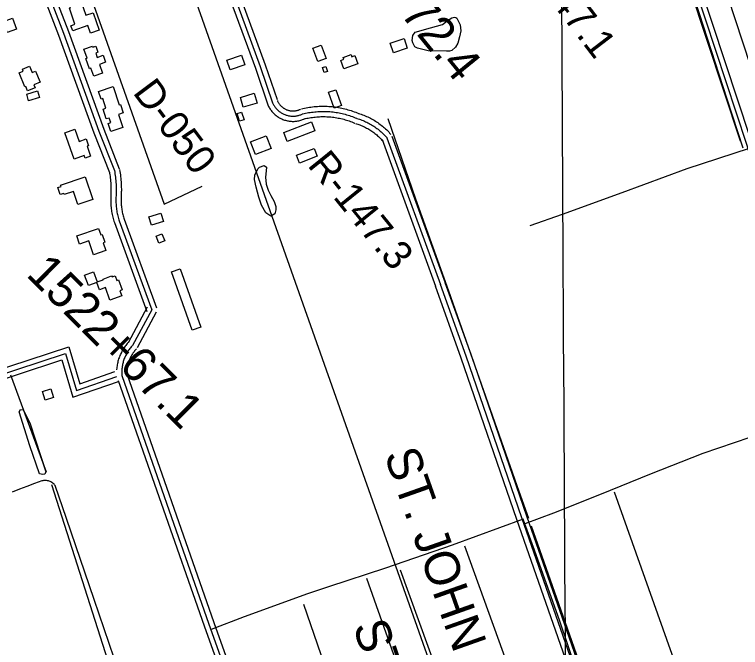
# Model space of a CAD drawing. Extents: x 3477039 to 3515015, y 546746 to 572297.
# Drawn here: x 3484941 to 3487029, y 555318 to 557139 of the extents above; entities that cross this region are included whole.
import ezdxf

# ---------------------------------------------------------------- set-up
doc = ezdxf.new("R2010")
doc.units = 0
for name, color, linetype in [('V-BLDG-OTLN', 7, 'Continuous'), ('V-DTCH-CNTR', 7, 'Continuous'), ('V-GRID-MAJR', 7, 'Continuous'), ('V-RIVR-RANG-IDEN', 7, 'Continuous'), ('V-ROAD-CNTR', 7, 'Continuous'), ('V-SITE-VEGE', 7, 'Continuous'), ('V-SURV-IDEN', 7, 'Continuous'), ('V-TOPO-BNDY', 7, 'Continuous'), ('V-TOPO-GNAM-IDEN', 7, 'Continuous'), ('V-TOPO-SHOR', 7, 'Continuous')]:
    doc.layers.add(name, color=color, linetype=linetype)

msp = doc.modelspace()

# ---------------------------------------------------------------- linework, layer by layer
at = {"layer": 'V-BLDG-OTLN'}
for points in [[(3485132.2, 557175.7), (3485145.6, 557136.6), (3485167.1, 557144), (3485184.3, 557094.1), (3485159, 557085.4), (3485151.5, 557107.2), (3485108, 557092.3), (3485103, 557106.8), (3485114.4, 557110.7), (3485098.4, 557157.3), (3485102, 557158.5), (3485099.9, 557164.6)], [(3484919.8, 557087.2), (3484908.7, 557119.2), (3484935.3, 557128.4), (3484946.4, 557096.5)], [(3486021.1, 557056.3), (3486061, 557069.7), (3486070.3, 557042), (3486030.4, 557028.6)], [(3485168.7, 556961.4), (3485160.4, 556984.3), (3485156.5, 556982.9), (3485146, 557012), (3485149.8, 557013.3), (3485140.5, 557039.1), (3485165.2, 557048), (3485166.3, 557045.1), (3485174.3, 557048), (3485180.7, 557030.2), (3485174.3, 557027.9), (3485178.8, 557015.6), (3485195.3, 557021.6), (3485202.5, 557001.5), (3485185.2, 556995.3), (3485194.1, 556970.5)], [(3485822.8, 557050.4), (3485836.7, 557012.2), (3485812.8, 557003.4), (3485798.9, 557041.7)], [(3485603.5, 556993.9), (3485560.8, 556979.5), (3485551.1, 557007.9), (3485593.9, 557022.4)], [(3485928.3, 556997.3), (3485888.2, 556982.6), (3485879.2, 557007), (3485887.8, 557010.2), (3485885.9, 557015.3), (3485908.6, 557023.6), (3485910.9, 557017.3), (3485919.7, 557020.6)], [(3485001.5, 556975.8), (3485014.2, 556944.4), (3484996, 556937.1), (3484999.8, 556927.8), (3484978.5, 556919.2), (3484973.3, 556932.1), (3484970.4, 556930.9), (3484954, 556971.3), (3484966.1, 556976.2), (3484963.7, 556982), (3484984.3, 556990.3), (3484991.7, 556971.9)], [(3485831.3, 556971.8), (3485826.1, 556986.1), (3485836, 556989.7), (3485841.2, 556975.4)], [(3485224.6, 556931.5), (3485241.6, 556878.7), (3485245.1, 556879.9), (3485252.8, 556855.9), (3485239.8, 556851.7), (3485252.2, 556813.5), (3485217.7, 556802.3), (3485210.1, 556825.9), (3485217.5, 556828.3), (3485213.4, 556841.2), (3485204.5, 556838.4), (3485195.4, 556866.6), (3485203.3, 556869.1), (3485194.3, 556897.2), (3485189.7, 556895.7), (3485182.5, 556917.9)], [(3485006.9, 556919.2), (3485012.6, 556900.4), (3484981.4, 556891), (3484975.7, 556909.7)], [(3485590.3, 556900.5), (3485630.1, 556912.4), (3485638.5, 556884.1), (3485598.7, 556872.3)], [(3485864.6, 556922.7), (3485881.1, 556876.8), (3485860.4, 556869.3), (3485843.8, 556915.2)], [(3485588.1, 556832), (3485581.1, 556854.4), (3485593.8, 556858.4), (3485600.8, 556835.9)], [(3485804.6, 556804.6), (3485724.6, 556773.8), (3485714.8, 556799.2), (3485794.8, 556830)], [(3485112.1, 556722.9), (3485085.2, 556798.7), (3485114.1, 556808.9), (3485126.6, 556773.8), (3485146.7, 556780.9), (3485153.6, 556761.4), (3485149.5, 556760), (3485159.6, 556731.4), (3485144.2, 556725.9), (3485141.5, 556733.3)], [(3485678.9, 556753.5), (3485633.5, 556735.9), (3485619.1, 556772.8), (3485664.5, 556790.4)], [(3485751.5, 556734.1), (3485802.4, 556753.8), (3485811.2, 556731.2), (3485760.3, 556711.5)], [(3485165.6, 556607.2), (3485123.1, 556592.7), (3485110.3, 556630.2), (3485083.4, 556621), (3485082.3, 556624.2), (3485072.4, 556620.8), (3485065.4, 556641.3), (3485074.6, 556644.4), (3485073.3, 556648), (3485143.6, 556671.9)], [(3485361.8, 556567.9), (3485369.5, 556543.9), (3485334.4, 556532.6), (3485326.6, 556556.6)], [(3485203.1, 556460.3), (3485168, 556448.1), (3485154.2, 556487.9), (3485127.6, 556478.7), (3485119.5, 556502), (3485182.5, 556523.8), (3485189, 556504.9), (3485192.9, 556506.2), (3485200.5, 556484.1), (3485195.4, 556482.4)], [(3485347.7, 556500.9), (3485364.6, 556507.9), (3485372.7, 556488.1), (3485355.8, 556481.1)], [(3485249.1, 556329.9), (3485215.3, 556317.5), (3485202.2, 556353.3), (3485185.4, 556347.1), (3485177.6, 556368.2), (3485153.2, 556359.3), (3485142.1, 556389.4), (3485167.9, 556398.9), (3485178.7, 556369.6), (3485196, 556375.9), (3485195.3, 556377.9), (3485220, 556387), (3485221.1, 556384), (3485229.8, 556387.2), (3485234.8, 556373.7), (3485239.7, 556375.5), (3485250.3, 556346.6), (3485243.9, 556344.2)], [(3485451.5, 556231.1), (3485392.3, 556398.4), (3485417, 556407.1), (3485476.2, 556239.8)], [(3485053.3, 556037.3), (3485029.3, 556029.5), (3485021.1, 556054.7), (3485045.1, 556062.5)]]:
    msp.add_lwpolyline(points, close=True, dxfattribs=at)
at = {"layer": 'V-DTCH-CNTR'}
for points in [[(3487053.5, 556754), (3486874.7, 556694.8), (3486687.1, 556625.7), (3486515.8, 556564.1), (3486422.4, 556531.5)], [(3487295.3, 556008.9), (3487100.7, 555937.9), (3486920.7, 555876.4), (3486767.2, 555815.8), (3486628.3, 555759.5), (3486490.6, 555704.7), (3486408.3, 555673.5)], [(3485241.5, 555244.9), (3485170.2, 555456.6), (3485090, 555689.3), (3485057.8, 555783.9), (3485056.2, 555786.1), (3485054.3, 555788.1), (3485052.3, 555789.9), (3485050.2, 555791.6), (3485048, 555793.2), (3485045.6, 555794.5), (3485043.2, 555795.7), (3485040.6, 555796.7), (3485038, 555797.5), (3485035.4, 555798), (3485032.7, 555798.4), (3485030, 555798.6), (3485027.3, 555798.6), (3485024.5, 555798.3), (3485021.9, 555797.9), (3485019.2, 555797.2), (3484997.9, 555789.5), (3484976.6, 555781.6), (3484955.4, 555773.4), (3484934.3, 555765)], [(3486403.2, 555687.8), (3486199.1, 555612.9), (3486007.6, 555546.7), (3485843.5, 555492.5), (3485783, 555472.9), (3485601.1, 555406.2), (3485505.9, 555370.4)], [(3487294.2, 553160.7), (3487226.6, 553354.4), (3487156.8, 553554), (3487103.2, 553706.9), (3487044.6, 553875.3), (3486981, 554053.9), (3486906.5, 554261.1), (3486850.6, 554426.2), (3486786.6, 554604.1), (3486716.4, 554802.9), (3486664.4, 554948.7), (3486577, 555192.3), (3486508.8, 555393.9), (3486436.6, 555597.8), (3486408.3, 555673.5), (3486403.2, 555687.8)]]:
    msp.add_lwpolyline(points, dxfattribs=at)
at = {"layer": 'V-GRID-MAJR'}
msp.add_spline([(3486543.6, 552138.8), (3486509.2, 558197.8), (3486474.8, 564258.8), (3486440.4, 570319.8), (3486440.4, 570321.7)], degree=3, dxfattribs=at)
at = {"layer": 'V-ROAD-CNTR'}
for points in [[(3487028.4, 556774.6), (3486883.8, 557212.5), (3486761.5, 557596.1), (3486680.6, 557855), (3486558.6, 558234.3), (3486503.2, 558387.9), (3486471.5, 558520.7)], [(3487292.8, 556012.9), (3487146.9, 556436.9), (3487047.2, 556765.5), (3486898.1, 557217.1), (3486775.8, 557600.6), (3486694.9, 557859.6), (3486572.8, 558239.2), (3486517.6, 558392.2), (3486486.1, 558524.2)], [(3487056.6, 556784.7), (3486912.4, 557221.8), (3486790.1, 557605.1), (3486709.2, 557864.1), (3486587, 558244), (3486532, 558396.5), (3486500.7, 558527.7)], [(3485337, 557728.4), (3485345.7, 557736.1), (3485456, 557501), (3485543.2, 557273.2), (3485647.6, 556989.4), (3485683, 556885.1)], [(3485340.7, 557711.5), (3485442.2, 557495.1), (3485529.1, 557268), (3485633.5, 556984.4), (3485670.2, 556876.1)], [(3484944, 557403.4), (3484973, 557367.2), (3485081.8, 557085), (3485183.4, 556803.8), (3485227.9, 556690.1)], [(3484965.1, 557401.1), (3484986.2, 557374.7), (3485095.8, 557090.3), (3485197.4, 556809.1), (3485241.9, 556695.5)], [(3484941.8, 557382.2), (3484959.9, 557359.6), (3485067.7, 557079.8), (3485169.3, 556798.5), (3485214, 556684.6)], [(3485594.5, 557177.3), (3485661.7, 556994.4), (3485695.8, 556894.1)], [(3485696.6, 556891.3), (3485697.5, 556889.5), (3485698.2, 556887.9), (3485699.1, 556886.4), (3485699.9, 556884.9), (3485700.9, 556883.5), (3485701.8, 556882), (3485702.9, 556880.7), (3485703.9, 556879.3), (3485705.1, 556878), (3485706.2, 556876.7), (3485707.5, 556875.5), (3485708.7, 556874.3), (3485710, 556873.2), (3485711.4, 556872.1), (3485712.7, 556871), (3485714.2, 556870), (3485715.6, 556869.1), (3485717.1, 556868.2), (3485718.6, 556867.3), (3485720.1, 556866.5), (3485721.7, 556865.8), (3485723.3, 556865.1), (3485724.9, 556864.5), (3485726.5, 556863.9), (3485728.2, 556863.4), (3485729.9, 556863), (3485731.6, 556862.6), (3485733.3, 556862.3), (3485735, 556862), (3485736.7, 556861.8), (3485738.4, 556861.7), (3485740.1, 556861.6), (3485741.9, 556861.6), (3485743.6, 556861.6), (3485745.3, 556861.7), (3485747, 556861.9), (3485748.8, 556862.1), (3485750.5, 556862.4), (3485752.2, 556862.7), (3485753.8, 556863.1), (3485755.5, 556863.6), (3485757.2, 556864.1), (3485758.8, 556864.7), (3485760.4, 556865.3), (3485762, 556866), (3485763, 556866.5)], [(3485669.3, 556878.9), (3485670.4, 556876.6), (3485671.6, 556874.1), (3485672.9, 556871.7), (3485674.3, 556869.3), (3485675.8, 556866.9), (3485677.4, 556864.6), (3485679.1, 556862.4), (3485680.8, 556860.2), (3485682.6, 556858.1), (3485684.5, 556856), (3485686.5, 556854), (3485688.5, 556852.1), (3485690.6, 556850.3), (3485692.8, 556848.5), (3485695, 556846.8), (3485697.3, 556845.2), (3485699.6, 556843.7), (3485702, 556842.2), (3485704.5, 556840.9), (3485706.9, 556839.6), (3485709.5, 556838.4), (3485712, 556837.3), (3485714.6, 556836.3), (3485717.3, 556835.4), (3485720, 556834.6), (3485722.7, 556833.9), (3485725.4, 556833.3), (3485728.1, 556832.7), (3485730.9, 556832.3), (3485733.6, 556832), (3485736.4, 556831.7), (3485739.2, 556831.6), (3485742, 556831.6), (3485744.8, 556831.6), (3485747.6, 556831.8), (3485750.4, 556832), (3485753.1, 556832.4), (3485755.9, 556832.9), (3485758.6, 556833.4), (3485761.3, 556834.1), (3485764, 556834.8), (3485766.7, 556835.6), (3485769.3, 556836.6), (3485771.9, 556837.6), (3485774.4, 556838.7), (3485775.8, 556839.4)], [(3485683, 556885.1), (3485683.9, 556883.1), (3485684.9, 556881), (3485686, 556879), (3485687.1, 556877.1), (3485688.4, 556875.2), (3485689.6, 556873.3), (3485691, 556871.5), (3485692.4, 556869.7), (3485693.9, 556868), (3485695.4, 556866.4), (3485697, 556864.8), (3485698.6, 556863.2), (3485700.3, 556861.7), (3485702.1, 556860.3), (3485703.9, 556858.9), (3485705.7, 556857.6), (3485707.6, 556856.4), (3485709.5, 556855.2), (3485711.5, 556854.1), (3485713.5, 556853.1), (3485715.6, 556852.1), (3485717.7, 556851.2), (3485719.8, 556850.4), (3485721.9, 556849.7), (3485724.1, 556849), (3485726.3, 556848.4), (3485728.5, 556847.9), (3485730.7, 556847.5), (3485732.9, 556847.2), (3485735.2, 556846.9), (3485737.4, 556846.7), (3485739.7, 556846.6), (3485741.9, 556846.6), (3485744.2, 556846.6), (3485746.5, 556846.7), (3485748.7, 556847), (3485750.9, 556847.2), (3485753.2, 556847.6), (3485755.4, 556848.1), (3485757.6, 556848.6), (3485759.8, 556849.2), (3485761.9, 556849.9), (3485764.1, 556850.6), (3485766.2, 556851.5), (3485768.2, 556852.4), (3485769.4, 556852.9)], [(3485765.9, 556867.5), (3485770.3, 556868.6), (3485774.9, 556869.6), (3485779.5, 556870.5), (3485784, 556871.4), (3485788.7, 556872.1), (3485793.3, 556872.8), (3485797.9, 556873.4), (3485802.6, 556873.9), (3485807.2, 556874.4), (3485811.9, 556874.7), (3485816.5, 556875), (3485821.2, 556875.2), (3485825.9, 556875.3), (3485830.6, 556875.3), (3485835.2, 556875.2), (3485839.9, 556875), (3485844.6, 556874.8), (3485849.2, 556874.4), (3485853.9, 556874), (3485858.5, 556873.5), (3485863.2, 556872.9), (3485867.8, 556872.3), (3485872.4, 556871.5), (3485877, 556870.7), (3485881.6, 556869.8), (3485886.2, 556868.7), (3485890.7, 556867.7), (3485895.2, 556866.5), (3485899.7, 556865.2), (3485904.2, 556863.9), (3485908.7, 556862.5), (3485913.1, 556861), (3485917.5, 556859.4), (3485921.9, 556857.8), (3485926.2, 556856), (3485930.5, 556854.2), (3485931, 556854)], [(3485769.4, 556852.9), (3485773.7, 556854), (3485778, 556854.9), (3485782.3, 556855.8), (3485786.6, 556856.6), (3485791, 556857.3), (3485795.3, 556858), (3485799.7, 556858.5), (3485804.1, 556859), (3485808.5, 556859.4), (3485812.9, 556859.8), (3485817.2, 556860), (3485821.6, 556860.2), (3485826, 556860.3), (3485830.4, 556860.3), (3485834.8, 556860.2), (3485839.2, 556860), (3485843.6, 556859.8), (3485848, 556859.5), (3485852.4, 556859.1), (3485856.8, 556858.6), (3485861.2, 556858.1), (3485865.5, 556857.4), (3485869.9, 556856.7), (3485874.2, 556855.9), (3485878.5, 556855.1), (3485882.8, 556854.1), (3485887.1, 556853.1), (3485891.3, 556852), (3485895.6, 556850.8), (3485899.8, 556849.6), (3485904, 556848.2), (3485908.2, 556846.8), (3485912.3, 556845.3), (3485916.4, 556843.8), (3485920.5, 556842.2), (3485924.6, 556840.4), (3485925, 556840.2)], [(3485929.7, 556854.6), (3485933.5, 556853.4), (3485937.5, 556852.1), (3485941.4, 556850.7), (3485945.2, 556849.2), (3485949.1, 556847.7), (3485952.9, 556846), (3485956.7, 556844.3), (3485960.4, 556842.5), (3485964.1, 556840.7), (3485967.8, 556838.7), (3485971.4, 556836.7), (3485975, 556834.6), (3485978.5, 556832.4), (3485982, 556830.2), (3485985.4, 556827.9), (3485988.8, 556825.5), (3485992.1, 556823), (3485995.4, 556820.5), (3485998.6, 556817.9), (3486001.8, 556815.2), (3486004.9, 556812.5), (3486008, 556809.7), (3486011, 556806.9), (3486013.9, 556804), (3486016.8, 556801), (3486019.6, 556797.9), (3486022.3, 556794.9), (3486023.1, 556794)], [(3485773, 556838.3), (3485777.1, 556839.4), (3485781.1, 556840.3), (3485785.2, 556841.1), (3485789.2, 556841.8), (3485793.3, 556842.5), (3485797.4, 556843.1), (3485801.5, 556843.6), (3485805.6, 556844.1), (3485809.7, 556844.5), (3485813.8, 556844.8), (3485818, 556845), (3485822.1, 556845.2), (3485826.2, 556845.3), (3485830.3, 556845.3), (3485834.5, 556845.2), (3485838.6, 556845), (3485842.7, 556844.8), (3485846.8, 556844.5), (3485850.9, 556844.2), (3485855, 556843.7), (3485859.1, 556843.2), (3485863.2, 556842.6), (3485867.3, 556841.9), (3485871.4, 556841.2), (3485875.4, 556840.4), (3485879.4, 556839.5), (3485883.5, 556838.5), (3485887.5, 556837.5), (3485891.4, 556836.4), (3485895.4, 556835.2), (3485899.3, 556834), (3485903.2, 556832.7), (3485907.1, 556831.3), (3485911, 556829.8), (3485914.8, 556828.3), (3485918.7, 556826.6), (3485919.1, 556826.5)], [(3485920.9, 556825.9), (3485924.4, 556824.8), (3485927.7, 556823.7), (3485931, 556822.5), (3485934.3, 556821.3), (3485937.6, 556820), (3485940.8, 556818.6), (3485944, 556817.1), (3485947.2, 556815.6), (3485950.3, 556814), (3485953.4, 556812.4), (3485956.5, 556810.7), (3485959.5, 556808.9), (3485962.5, 556807), (3485965.5, 556805.1), (3485968.4, 556803.2), (3485971.2, 556801.1), (3485974.1, 556799.1), (3485976.9, 556796.9), (3485979.6, 556794.7), (3485982.3, 556792.5), (3485984.9, 556790.1), (3485987.5, 556787.8), (3485990.1, 556785.3), (3485992.6, 556782.9), (3485995, 556780.3), (3485997.4, 556777.8), (3485999.8, 556775.1), (3486000.4, 556774.3)], [(3485925.3, 556840.2), (3485929, 556839.1), (3485932.6, 556837.9), (3485936.2, 556836.6), (3485939.8, 556835.3), (3485943.3, 556833.8), (3485946.8, 556832.3), (3485950.3, 556830.7), (3485953.8, 556829.1), (3485957.2, 556827.3), (3485960.6, 556825.5), (3485963.9, 556823.7), (3485967.2, 556821.7), (3485970.5, 556819.7), (3485973.7, 556817.7), (3485976.9, 556815.5), (3485980, 556813.3), (3485983.1, 556811), (3485986.1, 556808.7), (3485989.1, 556806.3), (3485992.1, 556803.8), (3485994.9, 556801.3), (3485997.8, 556798.7), (3486000.5, 556796.1), (3486003.3, 556793.4), (3486005.9, 556790.7), (3486008.5, 556787.9), (3486011.1, 556785), (3486011.8, 556784.2)], [(3486011.8, 556784.2), (3486165.4, 556362.5)], [(3486025.9, 556789.3), (3486179.5, 556367.6)], [(3485997.7, 556779), (3486151.3, 556357.4)], [(3485213.2, 556687.4), (3485214, 556682.8), (3485214.7, 556678.2), (3485215.4, 556673.6), (3485216, 556669), (3485216.5, 556664.4), (3485216.9, 556659.8), (3485217.3, 556655.2), (3485217.6, 556650.5), (3485217.8, 556645.9), (3485217.9, 556641.3), (3485218, 556636.6), (3485218, 556632), (3485217.9, 556629.8)], [(3485227.9, 556690.1), (3485228.8, 556685.3), (3485229.6, 556680.5), (3485230.3, 556675.6), (3485230.9, 556670.8), (3485231.4, 556665.9), (3485231.9, 556661.1), (3485232.3, 556656.2), (3485232.6, 556651.3), (3485232.8, 556646.5), (3485232.9, 556641.6), (3485233, 556636.7), (3485233, 556631.8), (3485232.9, 556629.6)], [(3485242.7, 556692.7), (3485243.6, 556687.8), (3485244.4, 556682.7), (3485245.1, 556677.6), (3485245.8, 556672.6), (3485246.3, 556667.5), (3485246.8, 556662.4), (3485247.2, 556657.2), (3485247.5, 556652.1), (3485247.8, 556647), (3485247.9, 556641.9), (3485248, 556636.8), (3485248, 556631.7), (3485247.9, 556629.3)], [(3485217.9, 556629.8), (3485217.4, 556601)], [(3485232.9, 556629.6), (3485232.4, 556600.8)], [(3485247.9, 556629.3), (3485247.4, 556600.5)], [(3485217.4, 556600.4), (3485217.5, 556596.5), (3485217.7, 556592.4), (3485218, 556588.3), (3485218.4, 556584.2), (3485218.8, 556580.2), (3485219.3, 556576.1), (3485220, 556572), (3485220.7, 556568), (3485221.5, 556564), (3485222.3, 556560), (3485223.3, 556556), (3485224.3, 556552), (3485225.5, 556548.1), (3485226.7, 556544.2), (3485227.9, 556540.6)], [(3485232.4, 556600.8), (3485232.5, 556597), (3485232.7, 556593.2), (3485233, 556589.5), (3485233.3, 556585.7), (3485233.7, 556581.9), (3485234.2, 556578.2), (3485234.8, 556574.5), (3485235.4, 556570.7), (3485236.1, 556567), (3485237, 556563.3), (3485237.8, 556559.7), (3485238.8, 556556), (3485239.8, 556552.4), (3485241, 556548.8), (3485242.1, 556545.4)], [(3485247.4, 556601.1), (3485247.5, 556597.5), (3485247.7, 556594.1), (3485247.9, 556590.6), (3485248.2, 556587.2), (3485248.6, 556583.7), (3485249, 556580.3), (3485249.6, 556576.9), (3485250.2, 556573.5), (3485250.8, 556570.1), (3485251.6, 556566.7), (3485252.4, 556563.3), (3485253.3, 556560), (3485254.2, 556556.7), (3485255.2, 556553.4), (3485256.3, 556550.1)], [(3485228, 556540.2), (3485321.2, 556284.7)], [(3485242.1, 556545.4), (3485335.3, 556289.9)], [(3485256.2, 556550.5), (3485349.4, 556295)], [(3487294.1, 553191), (3487150.9, 553595), (3487107.1, 553729.3), (3486886.8, 554352.8), (3486672.8, 554955.4), (3486414.1, 555696.1), (3486253.8, 556160.8), (3486179.5, 556367.6)], [(3487294.6, 553099.8), (3487290.4, 553111.6), (3487122.5, 553585.3), (3487078.7, 553719.7), (3486858.5, 554342.7), (3486644.5, 554945.4), (3486385.7, 555686.2), (3486225.5, 556150.9), (3486151.3, 556357.4)], [(3487294.3, 553145.3), (3487136.7, 553590.2), (3487092.9, 553724.5), (3486872.6, 554347.8), (3486658.7, 554950.4), (3486399.9, 555691.1), (3486239.6, 556155.8), (3486165.4, 556362.5)], [(3485322.1, 556296.9), (3485267.2, 556194.4)], [(3485335.3, 556289.9), (3485280.4, 556187.3)], [(3485348.5, 556282.8), (3485293.7, 556180.3)], [(3484812.3, 556089.8), (3485096.9, 556183.3), (3485128.6, 556076.6), (3485229.6, 556111.7)], [(3485269.4, 556197.5), (3485267.2, 556195.2), (3485265, 556192.6), (3485262.8, 556190), (3485260.7, 556187.3), (3485258.6, 556184.6), (3485256.7, 556181.8), (3485254.8, 556178.9), (3485253, 556176.1), (3485251.2, 556173.1), (3485249.6, 556170.1), (3485248, 556167.1), (3485246.5, 556164.1), (3485245.1, 556160.9), (3485243.7, 556157.8), (3485242.5, 556154.6), (3485241.3, 556151.4), (3485240.2, 556148.2), (3485239.2, 556144.9), (3485238.3, 556141.6), (3485237.5, 556138.3), (3485236.7, 556135), (3485236.1, 556131.6), (3485235.5, 556128.3), (3485235.1, 556124.9), (3485234.7, 556121.5), (3485234.4, 556118.1), (3485234.4, 556117.3)], [(3485280.4, 556187.3), (3485278.4, 556185.1), (3485276.4, 556182.9), (3485274.5, 556180.5), (3485272.6, 556178.2), (3485270.8, 556175.8), (3485269, 556173.3), (3485267.4, 556170.8), (3485265.8, 556168.2), (3485264.2, 556165.6), (3485262.8, 556163), (3485261.4, 556160.3), (3485260, 556157.6), (3485258.8, 556154.9), (3485257.6, 556152.1), (3485256.5, 556149.3), (3485255.4, 556146.5), (3485254.5, 556143.6), (3485253.6, 556140.7), (3485252.8, 556137.8), (3485252.1, 556134.9), (3485251.4, 556132), (3485250.9, 556129), (3485250.4, 556126), (3485250, 556123), (3485249.6, 556120), (3485249.4, 556117), (3485249.2, 556114), (3485249.1, 556111), (3485249.1, 556108), (3485249.1, 556105), (3485249.3, 556102), (3485249.4, 556100.8)], [(3484857.6, 555925), (3484800.9, 556070.3), (3485087, 556164.2), (3485118.6, 556057.3), (3485234.6, 556097.6)], [(3485291.4, 556177.1), (3485289.5, 556175.1), (3485287.8, 556173.1), (3485286.1, 556171.1), (3485284.5, 556169), (3485282.9, 556166.9), (3485281.4, 556164.8), (3485280, 556162.6), (3485278.6, 556160.4), (3485277.2, 556158.2), (3485276, 556155.9), (3485274.7, 556153.6), (3485273.6, 556151.2), (3485272.5, 556148.8), (3485271.5, 556146.4), (3485270.5, 556144), (3485269.6, 556141.5), (3485268.8, 556139), (3485268, 556136.5), (3485267.3, 556134), (3485266.7, 556131.5), (3485266.1, 556128.9), (3485265.6, 556126.3), (3485265.2, 556123.8), (3485264.8, 556121.2), (3485264.5, 556118.6), (3485264.4, 556117.3)], [(3484871.6, 555930.4), (3484820.6, 556061), (3485077, 556145.2), (3485108.7, 556038), (3485239.5, 556083.4)], [(3485264.4, 556117.2), (3485264.3, 556116), (3485264.2, 556113.3), (3485264.1, 556110.7), (3485264.1, 556108.1), (3485264.1, 556105.5), (3485264.3, 556102.8), (3485264.3, 556101.8)], [(3485249.4, 556100.8), (3485499.8, 555385.3), (3485808.2, 554521.8)], [(3485263.5, 556105.8), (3485513.9, 555390.3), (3485827.6, 554512.1)], [(3485238.6, 556086.2), (3485485.7, 555380.3), (3485788.8, 554531.5)]]:
    msp.add_lwpolyline(points, dxfattribs=at)
at = {"layer": 'V-SITE-VEGE'}
for points in [[(3486183.4, 557033.4), (3486130.1, 557034.9), (3486099.3, 557041.8), (3486092.2, 557046.2), (3486086.4, 557057.3), (3486084.5, 557064.4), (3486086.5, 557078.7), (3486092.9, 557087.7), (3486136.8, 557100.4), (3486171.7, 557110.5), (3486184.7, 557120.3), (3486198.2, 557129.7), (3486206.1, 557131.6), (3486210.1, 557130), (3486212.5, 557128.8), (3486222.6, 557109), (3486224.1, 557091.6), (3486220.8, 557074.6), (3486215.5, 557056.9), (3486209.1, 557044.7), (3486198.4, 557035.7), (3486192.1, 557033.7)], [(3485677.7, 556558.9), (3485663.7, 556568.3), (3485650.8, 556590.3), (3485643.5, 556613.6), (3485635.3, 556642.1), (3485630.8, 556664.5), (3485631.8, 556676.6), (3485640.3, 556694.7), (3485645, 556700.3), (3485659, 556704.9), (3485665.5, 556700.2), (3485664.5, 556689), (3485662.5, 556671.3), (3485664.3, 556651.2), (3485670.2, 556633.5), (3485678, 556618), (3485687.7, 556600.7), (3485691.8, 556586.7), (3485692.2, 556577.4), (3485689.4, 556565.8)], [(3485012.3, 555817.9), (3484984.9, 555898.2), (3484953.8, 555995.8), (3484957.6, 556003.2), (3484965.5, 556002.3), (3484984.8, 555964.4), (3485030.5, 555823.8), (3485027.7, 555816.4), (3485022.1, 555815.5)]]:
    msp.add_lwpolyline(points, close=True, dxfattribs=at)
at = {"layer": 'V-TOPO-BNDY'}
msp.add_line((3485206.1, 557902.6), (3487242.5, 552142.9), dxfattribs=at)
at = {"layer": 'V-TOPO-SHOR'}
for p, q in [((3487124.2, 556786.6), (3486774.1, 557859)), ((3485033.1, 555822.9), (3484930.4, 556101.7)), ((3486920.5, 555048.6), (3486666.2, 555765.2)), ((3486234.6, 555611.1), (3486496.7, 554886.7)), ((3485953.3, 555517.2), (3486429.4, 554165.8))]:
    msp.add_line(p, q, dxfattribs=at)
for points in [[(3486721.6, 557730.9), (3486790, 557519), (3486875.8, 557246.2), (3486989.2, 556896.7), (3487035.3, 556755.3)], [(3485069.8, 557444.8), (3485370.7, 556593.5), (3485480.8, 556644.9)], [(3486014.4, 556839.7), (3486094.3, 556609), (3486188.5, 556344.5), (3486289.7, 556057.2), (3486385.1, 555784.4), (3486419.3, 555690.2)], [(3485502.8, 554443.1), (3485216.6, 555257.7), (3485047.8, 555786.2)], [(3486426.6, 555667.7), (3486517.3, 555409.2), (3486606.5, 555155.1), (3486674.8, 554962.3)], [(3486049.7, 555541.8), (3486527.5, 554224), (3486812.6, 554324.2)], [(3486704.7, 552790.6), (3486142.2, 554370.4), (3485772.3, 555441.6)]]:
    msp.add_lwpolyline(points, dxfattribs=at)

# ---------------------------------------------------------------- texts
at = {"layer": 'V-RIVR-RANG-IDEN'}
for s, rotation, p in [('R-147.1', 307.3988, (3486370.9, 557320.2)), ('D-050', 306.8019, (3485278.9, 556914.2)), ('R-147.3', 308.9449, (3485781.1, 556704.7))]:
    msp.add_text(s, height=83, rotation=rotation, dxfattribs=at).set_placement(p)
at = {"layer": 'V-SURV-IDEN'}
for s, rotation, p in [('1535+72.4', 309.1495, (3485810.8, 557432)), ('1522+67.1', 315.1983, (3484971.1, 556388.7))]:
    msp.add_text(s, height=100, rotation=rotation, dxfattribs=at).set_placement(p)
at = {"layer": 'V-TOPO-GNAM-IDEN'}
for s, rotation, p in [('ST. JOHN THE BAPTIST PARISH', 289.4873, (3486002.9, 555872.8)), ('ST. JAMES PARISH', 288.7434, (3485913, 555379.6))]:
    msp.add_text(s, height=100, rotation=rotation, dxfattribs=at).set_placement(p)

doc.saveas('drawing.dxf')
